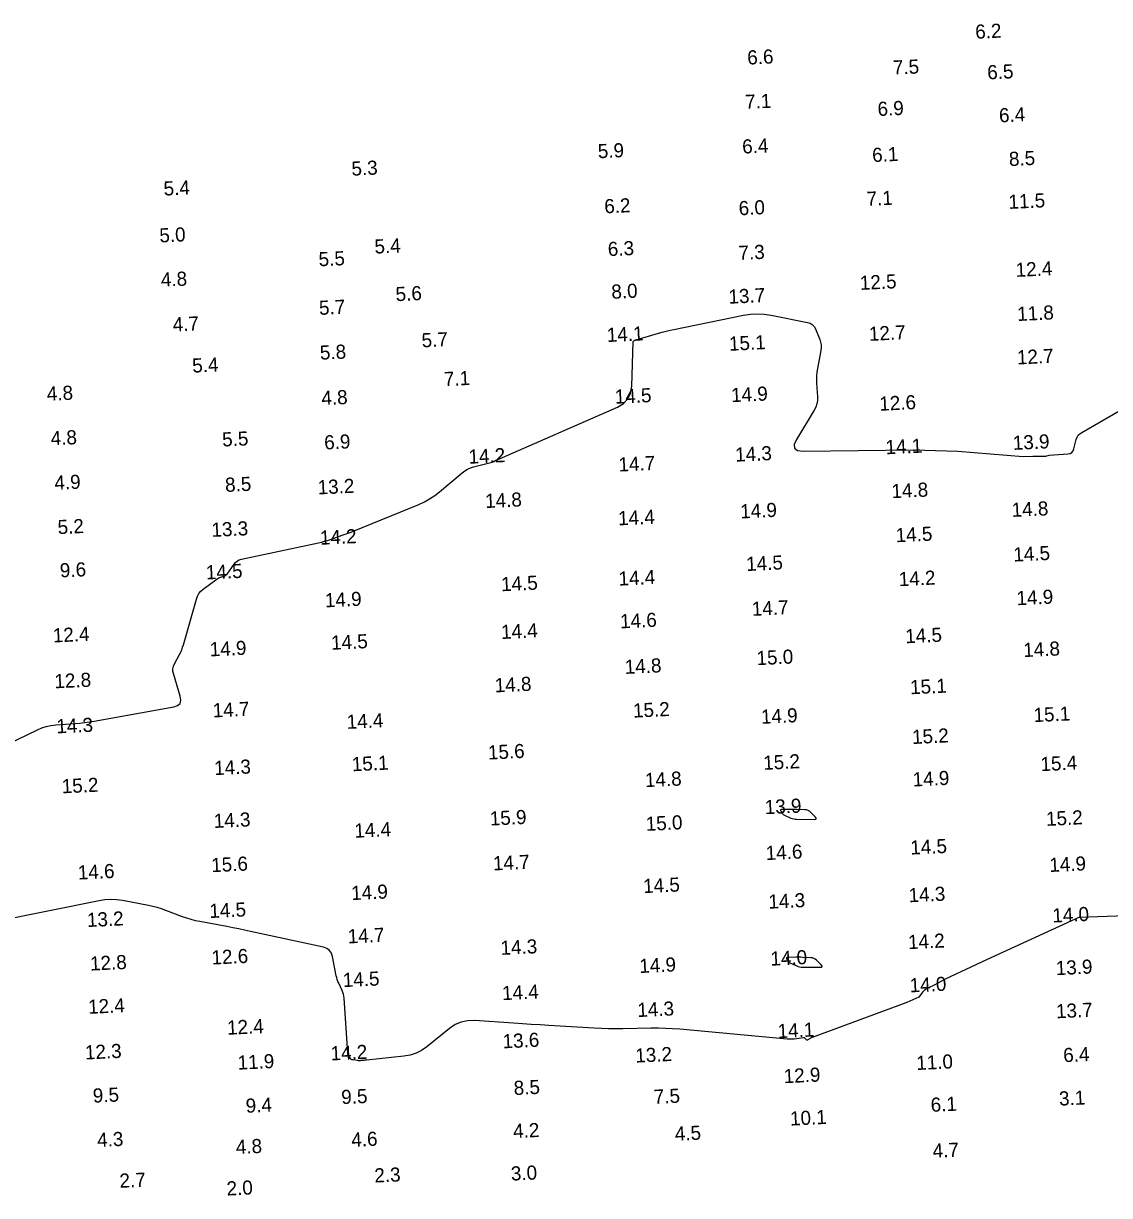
# Model space of a CAD drawing. Extents: x 824616 to 827440, y 158441 to 163197.
# Drawn here: x 825134.8 to 825519.8, y 161300 to 161715.4 of the extents above; entities that cross this region are included whole.
import ezdxf

# ---------------------------------------------------------------- set-up
doc = ezdxf.new("R2010")
doc.units = 0
doc.layers.add('V-CHAN-CONT-EL14', color=7, linetype='Continuous')
doc.layers.add('V-TOPO-SOUN', color=7, linetype='Continuous')

msp = doc.modelspace()

# ---------------------------------------------------------------- linework, layer by layer
at = {"layer": 'V-CHAN-CONT-EL14'}
for points in [[(825114.67, 161453.06), (825139.69, 161465.12), (825141.26, 161465.79), (825142.86, 161466.3), (825144.51, 161466.65), (825146.2, 161466.85), (825153.04, 161467.32), (825154.75, 161467.46), (825156.45, 161467.65), (825158.15, 161467.88), (825159.84, 161468.16), (825188.02, 161473.21), (825189.42, 161473.68), (825190.27, 161474.47), (825190.59, 161475.6), (825190.36, 161477.06), (825187.93, 161485), (825187.75, 161485.89), (825187.74, 161486.76), (825187.92, 161487.62), (825188.28, 161488.46), (825190.07, 161491.77), (825190.49, 161492.61), (825190.87, 161493.46), (825191.19, 161494.34), (825191.47, 161495.24), (825196.06, 161511.42), (825196.44, 161512.45), (825196.97, 161513.39), (825197.66, 161514.21), (825198.49, 161514.93), (825203.39, 161518.55), (825203.68, 161518.74), (825203.97, 161518.91), (825204.28, 161519.05), (825204.6, 161519.16), (825205.91, 161519.56), (825206.22, 161519.68), (825206.5, 161519.85), (825206.74, 161520.06), (825206.96, 161520.32), (825209.45, 161523.84), (825209.97, 161524.45), (825210.58, 161524.94), (825211.27, 161525.31), (825212.04, 161525.55), (825239.33, 161531.37), (825240.41, 161531.62), (825241.48, 161531.9), (825242.55, 161532.22), (825243.6, 161532.57), (825247.79, 161534.04), (825248.84, 161534.42), (825249.88, 161534.8), (825250.92, 161535.2), (825251.95, 161535.62), (825274.95, 161545.01), (825276.9, 161545.89), (825278.75, 161546.92), (825280.53, 161548.1), (825282.21, 161549.41), (825290.24, 161556.22), (825291.17, 161556.93), (825292.17, 161557.52), (825293.22, 161557.98), (825294.34, 161558.33), (825300.92, 161559.98), (825301.08, 161560.03), (825301.23, 161560.08), (825301.38, 161560.15), (825301.52, 161560.22), (825302.09, 161560.54), (825302.24, 161560.62), (825302.38, 161560.69), (825302.53, 161560.76), (825302.68, 161560.83), (825345.32, 161579.47), (825347.46, 161580.73), (825349.02, 161582.39), (825349.98, 161584.44), (825350.37, 161586.9), (825350.91, 161602.56), (825350.93, 161602.67), (825350.97, 161602.77), (825351.04, 161602.85), (825351.13, 161602.92), (825351.56, 161603.16), (825351.66, 161603.22), (825351.77, 161603.27), (825351.89, 161603.31), (825352, 161603.35), (825359.87, 161605.64), (825361.22, 161606.02), (825362.58, 161606.38), (825363.95, 161606.7), (825365.32, 161607), (825389.97, 161612.05), (825392.44, 161612.43), (825394.91, 161612.56), (825397.38, 161612.43), (825399.86, 161612.06), (825412.7, 161609.47), (825413.62, 161609.18), (825414.39, 161608.7), (825415.01, 161608.04), (825415.47, 161607.19), (825417.03, 161603.43), (825417.35, 161602.48), (825417.52, 161601.52), (825417.55, 161600.55), (825417.43, 161599.55), (825416.24, 161593.12), (825416.04, 161591.87), (825415.93, 161590.63), (825415.89, 161589.37), (825415.93, 161588.12), (825416.24, 161583.08), (825416.22, 161581.84), (825416.03, 161580.65), (825415.65, 161579.5), (825415.09, 161578.4), (825408.8, 161568.02), (825408, 161566.19), (825408.12, 161564.89), (825409.17, 161564.13), (825411.15, 161563.89), (825450.18, 161564.27), (825450.3, 161564.25), (825450.41, 161564.26), (825450.53, 161564.26), (825450.73, 161564.26), (825451.09, 161564.29), (825451.39, 161564.3), (825451.68, 161564.29), (825452.49, 161564.35), (825454.11, 161564.22), (825465.97, 161563.83)], [(825465.97, 161563.83), (825489.19, 161561.97), (825492.6, 161562.07), (825495.35, 161562.11), (825497.14, 161562.13), (825498.38, 161562.39), (825504.99, 161562.88), (825505.76, 161563.04), (825506.38, 161563.39), (825506.83, 161563.93), (825507.12, 161564.67), (825507.97, 161568), (825508.25, 161568.79), (825508.66, 161569.47), (825509.21, 161570.05), (825509.88, 161570.53), (825533.84, 161584.26)], [(825509.14, 161398.75), (825476.2, 161383.55), (825461.45, 161376.7), (825457.63, 161374.55), (825455.61, 161373.7), (825454.86, 161373.28), (825454.28, 161372.87), (825454.02, 161372.66), (825453.48, 161372.11), (825452.16, 161370.38), (825447.94, 161368.42), (825414.33, 161356.09), (825414.13, 161356.01), (825413.94, 161355.92), (825413.76, 161355.82), (825413.58, 161355.71), (825412.79, 161355.17), (825412.65, 161355.1), (825412.53, 161355.09), (825412.41, 161355.13), (825412.29, 161355.23), (825411.84, 161355.71), (825411.72, 161355.82), (825411.59, 161355.88), (825411.45, 161355.92), (825411.29, 161355.91), (825407.95, 161355.5), (825407.34, 161355.44), (825406.73, 161355.42), (825406.12, 161355.42), (825405.5, 161355.46), (825367.4, 161358.96), (825364.88, 161359.15), (825362.35, 161359.28), (825359.83, 161359.34), (825357.3, 161359.33), (825347.19, 161359.16), (825344.66, 161359.14), (825342.13, 161359.17), (825339.61, 161359.24), (825337.08, 161359.37), (825321.04, 161360.3), (825317.9, 161360.49), (825314.76, 161360.69), (825311.62, 161360.89), (825308.49, 161361.1), (825294.64, 161362.05), (825292.22, 161362), (825289.95, 161361.52), (825287.81, 161360.6), (825285.8, 161359.26), (825277.76, 161352.76), (825275.91, 161351.47), (825273.95, 161350.48), (825271.86, 161349.8), (825269.65, 161349.41), (825256.53, 161348.07), (825256.26, 161348.04), (825255.99, 161348.01), (825255.72, 161347.98), (825255.45, 161347.95), (825254.38, 161347.84), (825254.11, 161347.82), (825253.85, 161347.81), (825253.58, 161347.82), (825253.31, 161347.85), (825251.5, 161348.09), (825251.25, 161348.15), (825251.03, 161348.26), (825250.83, 161348.41), (825250.67, 161348.6), (825250.06, 161349.47), (825249.93, 161349.7), (825249.83, 161349.93), (825249.76, 161350.18), (825249.73, 161350.44), (825248.46, 161369.95), (825248.38, 161370.66), (825248.24, 161371.35), (825248.03, 161372.02), (825247.76, 161372.67), (825246.53, 161375.26), (825246.24, 161375.91), (825246, 161376.58), (825245.8, 161377.26), (825245.65, 161377.95), (825244.35, 161384.71), (825243.96, 161385.94), (825243.29, 161386.9), (825242.34, 161387.59), (825241.13, 161388.02), (825215.26, 161393.67), (825213.15, 161394.12), (825211.05, 161394.55), (825208.94, 161394.97), (825206.83, 161395.36), (825197.29, 161397.12), (825195.73, 161397.44), (825194.19, 161397.83), (825192.67, 161398.29), (825191.16, 161398.82), (825185.18, 161401.08), (825183.68, 161401.61), (825182.16, 161402.08), (825180.61, 161402.48), (825179.05, 161402.81), (825169.81, 161404.56), (825167.74, 161404.85), (825165.68, 161404.94), (825163.62, 161404.83), (825161.56, 161404.52), (825124.51, 161397.04)], [(825509.14, 161398.75), (825567.91, 161400.83)]]:
    msp.add_lwpolyline(points, dxfattribs=at)
for points in [[(825403.95, 161435.24), (825404.12, 161435.1), (825404.32, 161434.99), (825406.81, 161433.84), (825407.31, 161433.65), (825407.81, 161433.51), (825408.32, 161433.42), (825408.85, 161433.39), (825415.13, 161433.34), (825415.6, 161433.39), (825415.81, 161433.55), (825415.77, 161433.81), (825415.48, 161434.18), (825413.8, 161435.86), (825413.36, 161436.23), (825412.87, 161436.5), (825412.35, 161436.68), (825411.77, 161436.75), (825408.85, 161436.88), (825408.27, 161436.9), (825407.68, 161436.91), (825407.1, 161436.91), (825406.51, 161436.89), (825403.46, 161436.8), (825403.27, 161436.77), (825403.17, 161436.69), (825403.16, 161436.56), (825403.23, 161436.39), (825403.68, 161435.58), (825403.8, 161435.4)], [(825406.02, 161382.82), (825406.19, 161382.68), (825406.39, 161382.57), (825408.88, 161381.42), (825409.37, 161381.23), (825409.87, 161381.09), (825410.39, 161381), (825410.92, 161380.97), (825417.19, 161380.92), (825417.66, 161380.97), (825417.87, 161381.13), (825417.84, 161381.39), (825417.54, 161381.76), (825415.87, 161383.44), (825415.42, 161383.81), (825414.94, 161384.08), (825414.41, 161384.26), (825413.84, 161384.33), (825410.92, 161384.46), (825410.33, 161384.48), (825409.75, 161384.49), (825409.16, 161384.49), (825408.58, 161384.47), (825405.53, 161384.38), (825405.34, 161384.35), (825405.24, 161384.27), (825405.22, 161384.14), (825405.29, 161383.97), (825405.74, 161383.16), (825405.87, 161382.98)]]:
    msp.add_lwpolyline(points, close=True, dxfattribs=at)

# ---------------------------------------------------------------- texts
at = {"layer": 'V-TOPO-SOUN'}
for s, p in [('6.2', (825472.26, 161710)), ('6.6', (825391.44, 161700.85)), ('7.5', (825443.08, 161697.3)), ('6.5', (825476.52, 161695.6)), ('7.1', (825390.67, 161685.13)), ('6.9', (825437.64, 161682.62)), ('6.4', (825480.69, 161680.35)), ('5.9', (825338.47, 161667.65)), ('6.4', (825389.65, 161669.3)), ('6.1', (825435.72, 161666.3)), ('8.5', (825484.21, 161664.89)), ('5.3', (825251.14, 161661.47)), ('5.4', (825184.56, 161654.42)), ('7.1', (825433.73, 161650.77)), ('11.5 ', (825484.04, 161649.69)), ('6.2', (825340.76, 161648.12)), ('6.0', (825388.41, 161647.44)), ('5.0', (825183.05, 161637.81)), ('5.4', (825259.3, 161633.86)), ('6.3', (825342.02, 161632.96)), ('5.5', (825239.51, 161629.36)), ('7.3', (825388.34, 161631.61)), ('12.4 ', (825486.58, 161625.6)), ('4.8', (825183.58, 161622.13)), ('12.5 ', (825431.36, 161620.99)), ('5.6', (825266.8, 161617)), ('8.0', (825343.28, 161617.85)), ('13.7 ', (825384.79, 161616.1)), ('5.7', (825239.64, 161612.14)), ('11.8 ', (825487.11, 161609.97)), ('4.7', (825187.78, 161606.25)), ('5.7', (825276.02, 161600.63)), ('14.1 ', (825341.66, 161602.52)), ('12.7 ', (825434.57, 161602.93)), ('5.8', (825239.96, 161596.26)), ('15.1 ', (825384.96, 161599.42)), ('5.4', (825194.71, 161591.68)), ('12.7 ', (825487.04, 161594.57)), ('7.1', (825283.91, 161586.9)), ('4.8', (825143.15, 161581.7)), ('4.8', (825240.49, 161580.16)), ('14.5 ', (825344.49, 161580.65)), ('14.9 ', (825385.72, 161581.21)), ('12.6 ', (825438.25, 161578.16)), ('4.8', (825144.53, 161565.92)), ('5.5', (825205.31, 161565.49)), ('6.9', (825241.48, 161564.43)), ('14.1 ', (825440.46, 161562.73)), ('13.9 ', (825485.58, 161564.28)), ('14.2 ', (825292.64, 161559.39)), ('14.3 ', (825387.16, 161560.11)), ('14.7 ', (825345.8, 161556.62)), ('4.9', (825145.84, 161550.14)), ('8.5', (825206.34, 161549.4)), ('13.2 ', (825239.16, 161548.51)), ('14.8 ', (825442.57, 161547.18)), ('14.8 ', (825298.53, 161543.68)), ('14.4 ', (825345.66, 161537.54)), ('14.9 ', (825388.95, 161539.99)), ('14.8 ', (825485.17, 161540.54)), ('5.2', (825146.99, 161534.43)), ('13.3 ', (825201.51, 161533.46)), ('14.2 ', (825239.95, 161530.67)), ('14.5 ', (825444.05, 161531.56)), ('14.5 ', (825485.77, 161524.71)), ('14.5 ', (825391.06, 161521.36)), ('9.6', (825147.78, 161519.09)), ('14.5 ', (825199.52, 161518.37)), ('14.5 ', (825304.18, 161514.19)), ('14.4 ', (825345.82, 161516.18)), ('14.2 ', (825445.16, 161515.98)), ('14.9 ', (825241.73, 161508.48)), ('14.9 ', (825486.9, 161509.23)), ('14.7 ', (825393.06, 161505.47)), ('14.6 ', (825346.36, 161501.03)), ('12.4 ', (825145.28, 161496.04)), ('14.4 ', (825304.16, 161497.27)), ('14.5 ', (825447.45, 161495.75)), ('14.5 ', (825243.92, 161493.45)), ('14.9 ', (825200.91, 161491.11)), ('15.0 ', (825394.74, 161488)), ('14.8 ', (825489.28, 161490.86)), ('14.8 ', (825348.02, 161484.89)), ('12.8 ', (825145.85, 161479.79)), ('14.8 ', (825301.93, 161478.35)), ('15.1 ', (825449.17, 161477.68)), ('14.7 ', (825201.96, 161469.47)), ('15.2 ', (825350.95, 161469.4)), ('14.9 ', (825396.3, 161467.21)), ('15.1 ', (825492.93, 161467.82)), ('14.3 ', (825146.53, 161463.82)), ('14.4 ', (825249.44, 161465.41)), ('15.2 ', (825449.87, 161460.05)), ('15.6 ', (825299.52, 161454.55)), ('15.1 ', (825251.27, 161450.39)), ('15.2 ', (825397.11, 161450.9)), ('15.4 ', (825495.4, 161450.43)), ('14.3 ', (825202.48, 161449.03)), ('15.2 ', (825148.45, 161442.57)), ('14.8 ', (825355.18, 161444.77)), ('14.9 ', (825450.07, 161445)), ('13.9 ', (825397.65, 161435.18)), ('14.3 ', (825202.32, 161430.29)), ('15.9 ', (825300.19, 161431.16)), ('15.0 ', (825355.47, 161429.27)), ('15.2 ', (825497.36, 161431.03)), ('14.4 ', (825252.17, 161426.82)), ('14.5 ', (825449.24, 161420.86)), ('14.6 ', (825397.98, 161418.91)), ('15.6 ', (825201.43, 161414.63)), ('14.7 ', (825301.3, 161415.25)), ('14.9 ', (825498.53, 161414.69)), ('14.6 ', (825154.14, 161412.01)), ('14.9 ', (825251.04, 161404.73)), ('14.5 ', (825354.54, 161407.21)), ('14.3 ', (825398.95, 161401.68)), ('14.3 ', (825448.64, 161403.96)), ('14.5 ', (825200.76, 161398.38)), ('14.0 ', (825499.59, 161396.78)), ('13.2 ', (825157.38, 161395.19)), ('14.7 ', (825249.82, 161389.38)), ('14.3 ', (825303.99, 161385.31)), ('14.2 ', (825448.43, 161387.35)), ('12.8 ', (825158.47, 161379.75)), ('12.6 ', (825201.53, 161381.9)), ('14.0 ', (825399.66, 161381.48)), ('14.9 ', (825353.18, 161378.89)), ('13.9 ', (825500.81, 161378.13)), ('14.5 ', (825248.07, 161373.9)), ('14.0 ', (825449.01, 161372.03)), ('14.4 ', (825304.52, 161369.27)), ('12.4 ', (825157.79, 161364.42)), ('14.3 ', (825352.48, 161363.28)), ('13.7 ', (825500.89, 161362.84)), ('12.4 ', (825207.04, 161357.01)), ('14.1 ', (825402.2, 161355.8)), ('13.6 ', (825304.72, 161352.19)), ('12.3 ', (825156.66, 161348.24)), ('14.2 ', (825243.74, 161347.91)), ('13.2 ', (825351.75, 161347.14)), ('6.4', (825503.45, 161347.28)), ('11.9 ', (825210.77, 161344.63)), ('11.0 ', (825451.35, 161344.51)), ('12.9 ', (825404.37, 161339.84)), ('8.5', (825308.66, 161335.65)), ('9.5', (825159.46, 161332.94)), ('9.5', (825247.53, 161332.43)), ('7.5', (825358.31, 161332.54)), ('6.1', (825456.47, 161329.68)), ('3.1', (825501.96, 161331.89)), ('9.4', (825213.66, 161329.34)), ('10.1 ', (825406.61, 161324.82)), ('4.3', (825160.98, 161317.22)), ('4.6', (825251.08, 161317.29)), ('4.2', (825308.45, 161320.38)), ('4.5', (825365.77, 161319.43)), ('4.8', (825210.15, 161314.73)), ('4.7', (825457.17, 161313.4)), ('3.0', (825307.65, 161305.31)), ('2.7', (825168.92, 161302.77)), ('2.3', (825259.26, 161304.63)), ('2.0', (825206.88, 161300.02))]:
    msp.add_text(s, height=5, rotation=2.7, dxfattribs=at).set_placement(p)

doc.saveas('drawing.dxf')
